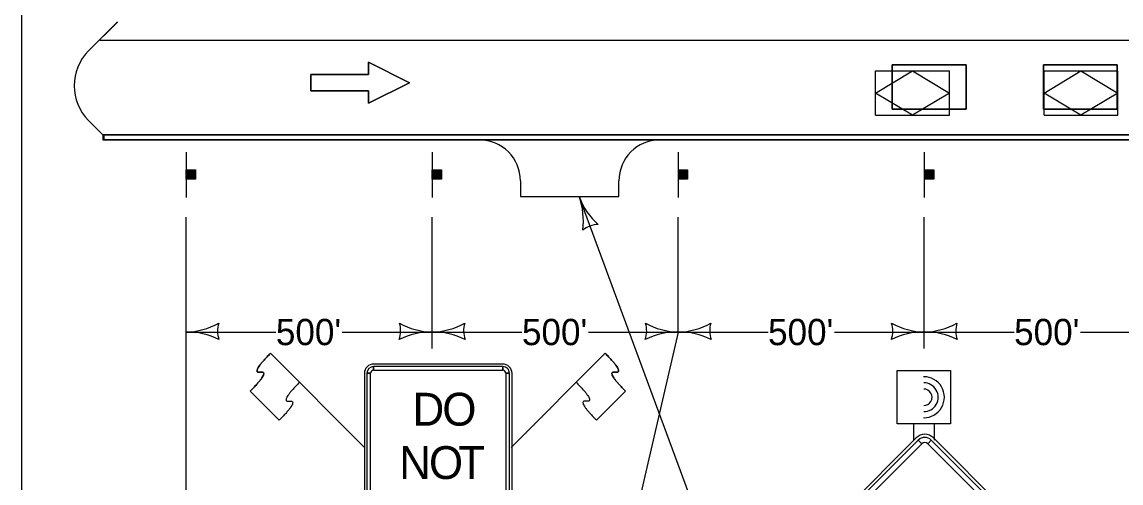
# Model space of a CAD drawing. Extents: x -2134934 to -2119606, y -2139046 to -2137036.
# Drawn here: x -2130232 to -2129562, y -2137877 to -2137596 of the extents above; entities that cross this region are included whole.
import ezdxf

# ---------------------------------------------------------------- set-up
doc = ezdxf.new("R2010")
doc.units = 0
for name, color, linetype in [('Default', 7, 'Continuous'), ('dsnCellElements', 7, 'Continuous'), ('dsnStdLabel', 7, 'Continuous'), ('dsnStdLineWork', 7, 'Continuous'), ('Level 2', 7, 'Continuous'), ('Level 4', 7, 'Continuous'), ('Level 5', 7, 'Continuous')]:
    doc.layers.add(name, color=color, linetype=linetype)

msp = doc.modelspace()

# ---------------------------------------------------------------- linework, layer by layer
at = {"layer": 'Default'}
msp.add_lwpolyline([(-2130231.95, -2137035.95), (-2127096.96, -2137035.95), (-2127096.96, -2139045.94), (-2130231.95, -2139045.94)], close=True, dxfattribs=at)
at = {"layer": 'dsnCellElements'}
for centre, radius, start, end in [((-2129932.23, -2137717.4), 42.5, 352.23545, 20.30794), ((-2129852.52, -2137687.9), 42.5, 200.30794, 228.38043), ((-2129880.01, -2137736.07), 16.42, 92.57459, 128.04129)]:
    msp.add_arc(centre, radius, start, end, dxfattribs=at)
at = {"layer": 'dsnStdLabel'}
for p, q in [((-2130023.11, -2137855.42), (-2130080.45, -2137798.12)), ((-2130080.45, -2137798.12), (-2130062.76, -2137815.8)), ((-2129933.82, -2137855.42), (-2129876.5, -2137798.11)), ((-2129876.5, -2137798.11), (-2129894.18, -2137815.79)), ((-2130023.24, -2137810.29), (-2130023.24, -2137919.04)), ((-2130021.68, -2137810.29), (-2130019.49, -2137810.29)), ((-2129938.87, -2137804.67), (-2130017.62, -2137804.67)), ((-2130017.62, -2137808.42), (-2130017.62, -2137806.23)), ((-2129938.87, -2137806.23), (-2129938.87, -2137808.42)), ((-2129936.99, -2137810.29), (-2129934.81, -2137810.29)), ((-2129933.24, -2137919.04), (-2129933.24, -2137810.29)), ((-2130075.13, -2137838.79), (-2130092.81, -2137821.12)), ((-2129881.8, -2137838.78), (-2129864.12, -2137821.1)), ((-2129686.95, -2137849.65), (-2129761.19, -2137923.9)), ((-2129685.62, -2137850.98), (-2129683.41, -2137853.19)), ((-2129679.88, -2137853.19), (-2129677.67, -2137850.98)), ((-2129602.1, -2137923.9), (-2129676.34, -2137849.65))]:
    msp.add_line(p, q, dxfattribs=at)
for points in [[(-2130021.68, -2137810.29), (-2130021.68, -2137919.04), (-2130019.49, -2137919.04), (-2130019.49, -2137810.29), (-2130021.68, -2137810.29)], [(-2129938.87, -2137806.23), (-2130017.62, -2137806.23), (-2130017.62, -2137808.42), (-2129938.87, -2137808.42), (-2129938.87, -2137806.23)], [(-2129934.81, -2137919.04), (-2129934.81, -2137810.29), (-2129936.99, -2137810.29), (-2129936.99, -2137919.04), (-2129934.81, -2137919.04)], [(-2129685.62, -2137850.98), (-2129759.87, -2137925.22), (-2129757.66, -2137927.43), (-2129683.41, -2137853.19), (-2129685.62, -2137850.98)], [(-2129603.42, -2137925.22), (-2129677.67, -2137850.98), (-2129679.88, -2137853.19), (-2129605.63, -2137927.43), (-2129603.42, -2137925.22)]]:
    msp.add_lwpolyline(points, close=True, dxfattribs=at)
for centre, radius, start, end in [((-2130017.62, -2137810.29), 5.62, 90.00021, 179.99985), ((-2130017.62, -2137810.29), 4.06, 90.00021, 179.99985), ((-2130017.62, -2137810.29), 1.87, 90.00021, 179.99985), ((-2129938.87, -2137810.29), 5.62, 0, 90.00021), ((-2129938.87, -2137810.29), 4.06, 0, 90.00021), ((-2129938.87, -2137810.29), 1.87, 0, 90.00021), ((-2129681.64, -2137854.96), 7.5, 44.99999, 134.99974), ((-2129681.64, -2137854.96), 5.62, 44.99999, 134.99974), ((-2129681.64, -2137854.96), 2.5, 44.99999, 134.99974)]:
    msp.add_arc(centre, radius, start, end, dxfattribs=at)
for points in [[(-2130092.81, -2137821.12), (-2130080.44, -2137808.74), (-2130092.82, -2137810.51), (-2130080.45, -2137798.12)], [(-2129864.12, -2137821.1), (-2129876.5, -2137808.72), (-2129864.12, -2137810.49), (-2129876.5, -2137798.11)], [(-2130062.76, -2137815.8), (-2130075.13, -2137828.19), (-2130062.76, -2137826.41), (-2130075.13, -2137838.79)], [(-2129894.18, -2137815.79), (-2129881.8, -2137828.17), (-2129894.17, -2137826.4), (-2129881.8, -2137838.78)]]:
    msp.add_open_spline(points, degree=2, dxfattribs=at)
at = {"layer": 'dsnStdLineWork'}
for p, q in [((-2129531.95, -2137607.66), (-2130184.45, -2137607.66)), ((-2129535.12, -2137665.16), (-2130182.57, -2137665.16)), ((-2130182.57, -2137665.16), (-2130182.57, -2137668.16)), ((-2130182.57, -2137668.16), (-2129497.55, -2137668.16)), ((-2130181.95, -2137665.16), (-2128681.95, -2137665.16)), ((-2130181.95, -2137668.16), (-2130181.95, -2137665.16))]:
    msp.add_line(p, q, dxfattribs=at)
for points in [[(-2128870.12, -2137665.16), (-2130182.57, -2137665.16)], [(-2128870.12, -2137668.16), (-2130182.57, -2137668.16)]]:
    msp.add_lwpolyline(points, dxfattribs=at)
at = {"layer": 'Level 2'}
for p, q in [((-2130173.78, -2137596.37), (-2130191.36, -2137613.95)), ((-2130173.79, -2137596.38), (-2130191.36, -2137613.95)), ((-2129701.47, -2137622.46), (-2129656.47, -2137622.46)), ((-2129701.47, -2137649.46), (-2129701.47, -2137622.46)), ((-2129656.47, -2137622.46), (-2129701.47, -2137622.46)), ((-2129701.47, -2137622.46), (-2129701.47, -2137649.46)), ((-2129656.47, -2137622.46), (-2129656.47, -2137649.46)), ((-2129656.47, -2137649.46), (-2129656.47, -2137622.46)), ((-2129609.28, -2137622.54), (-2129564.28, -2137622.54)), ((-2129609.28, -2137649.54), (-2129609.28, -2137622.54)), ((-2129564.28, -2137622.54), (-2129609.28, -2137622.54)), ((-2129609.28, -2137622.54), (-2129609.28, -2137649.54)), ((-2129564.28, -2137622.54), (-2129564.28, -2137649.54)), ((-2129564.28, -2137649.54), (-2129564.28, -2137622.54)), ((-2129711.63, -2137653.13), (-2129711.63, -2137626.13)), ((-2129711.63, -2137626.13), (-2129666.63, -2137626.13)), ((-2129666.63, -2137653.13), (-2129666.63, -2137626.13)), ((-2129608.95, -2137653.13), (-2129608.95, -2137626.13)), ((-2129608.95, -2137626.13), (-2129563.95, -2137626.13)), ((-2129563.95, -2137653.13), (-2129563.95, -2137626.13)), ((-2129656.47, -2137649.46), (-2129701.47, -2137649.46)), ((-2129701.47, -2137649.46), (-2129656.47, -2137649.46)), ((-2129564.28, -2137649.54), (-2129609.28, -2137649.54)), ((-2129609.28, -2137649.54), (-2129564.28, -2137649.54)), ((-2130191.36, -2137656.37), (-2130182.57, -2137665.16)), ((-2130191.36, -2137656.38), (-2130182.57, -2137665.16)), ((-2129711.63, -2137653.13), (-2129666.63, -2137653.13)), ((-2129608.95, -2137653.13), (-2129563.95, -2137653.13)), ((-2130182.57, -2137665.16), (-2128870.12, -2137665.16)), ((-2129843.13, -2137668.16), (-2129953.13, -2137668.16)), ((-2129639.46, -2137668.16), (-2129614.46, -2137668.16)), ((-2130131.95, -2137675.66), (-2130131.95, -2137703.16)), ((-2129981.95, -2137675.66), (-2129981.95, -2137703.16)), ((-2129831.95, -2137675.66), (-2129831.95, -2137703.16)), ((-2129681.95, -2137675.66), (-2129681.95, -2137703.16)), ((-2130131.54, -2137692.11), (-2130131.54, -2137686.52)), ((-2130131.26, -2137686.52), (-2130131.26, -2137692.11)), ((-2130130.99, -2137692.11), (-2130130.99, -2137686.52)), ((-2130130.73, -2137686.52), (-2130130.73, -2137692.11)), ((-2130130.51, -2137692.11), (-2130130.51, -2137686.52)), ((-2130130.3, -2137686.52), (-2130130.3, -2137692.11)), ((-2130129.96, -2137692.11), (-2130129.96, -2137686.52)), ((-2130129.7, -2137686.52), (-2130129.7, -2137692.11)), ((-2130129.47, -2137692.11), (-2130129.49, -2137686.52)), ((-2130129.16, -2137686.52), (-2130129.16, -2137692.11)), ((-2130128.78, -2137692.11), (-2130128.78, -2137686.52)), ((-2130128.35, -2137686.52), (-2130128.35, -2137692.11)), ((-2130128.12, -2137692.11), (-2130128.14, -2137686.52)), ((-2130127.71, -2137686.52), (-2130127.69, -2137692.11)), ((-2130127.49, -2137692.11), (-2130127.49, -2137686.52)), ((-2130127.17, -2137686.52), (-2130127.17, -2137692.11)), ((-2130126.94, -2137692.11), (-2130126.94, -2137686.52)), ((-2130126.62, -2137686.52), (-2130126.62, -2137692.11)), ((-2129981.54, -2137692.11), (-2129981.54, -2137686.52)), ((-2129981.26, -2137686.52), (-2129981.26, -2137692.11)), ((-2129980.99, -2137692.11), (-2129980.99, -2137686.52)), ((-2129980.73, -2137686.52), (-2129980.73, -2137692.11)), ((-2129980.51, -2137692.11), (-2129980.51, -2137686.52)), ((-2129980.3, -2137686.52), (-2129980.3, -2137692.11)), ((-2129979.96, -2137692.11), (-2129979.96, -2137686.52)), ((-2129979.7, -2137686.52), (-2129979.7, -2137692.11)), ((-2129979.47, -2137692.11), (-2129979.49, -2137686.52)), ((-2129979.16, -2137686.52), (-2129979.16, -2137692.11)), ((-2129978.78, -2137692.11), (-2129978.78, -2137686.52)), ((-2129978.35, -2137686.52), (-2129978.35, -2137692.11)), ((-2129978.12, -2137692.11), (-2129978.14, -2137686.52)), ((-2129977.71, -2137686.52), (-2129977.69, -2137692.11)), ((-2129977.49, -2137692.11), (-2129977.49, -2137686.52)), ((-2129977.17, -2137686.52), (-2129977.17, -2137692.11)), ((-2129976.94, -2137692.11), (-2129976.94, -2137686.52)), ((-2129976.62, -2137686.52), (-2129976.62, -2137692.11)), ((-2129831.54, -2137692.11), (-2129831.54, -2137686.52)), ((-2129831.26, -2137686.52), (-2129831.26, -2137692.11)), ((-2129830.99, -2137692.11), (-2129830.99, -2137686.52)), ((-2129830.73, -2137686.52), (-2129830.73, -2137692.11)), ((-2129830.51, -2137692.11), (-2129830.51, -2137686.52)), ((-2129830.3, -2137686.52), (-2129830.3, -2137692.11)), ((-2129829.96, -2137692.11), (-2129829.96, -2137686.52)), ((-2129829.7, -2137686.52), (-2129829.7, -2137692.11)), ((-2129829.47, -2137692.11), (-2129829.49, -2137686.52)), ((-2129829.16, -2137686.52), (-2129829.16, -2137692.11)), ((-2129828.78, -2137692.11), (-2129828.78, -2137686.52)), ((-2129828.35, -2137686.52), (-2129828.35, -2137692.11)), ((-2129828.12, -2137692.11), (-2129828.14, -2137686.52)), ((-2129827.71, -2137686.52), (-2129827.69, -2137692.11)), ((-2129827.49, -2137692.11), (-2129827.49, -2137686.52)), ((-2129827.17, -2137686.52), (-2129827.17, -2137692.11)), ((-2129826.94, -2137692.11), (-2129826.94, -2137686.52)), ((-2129826.62, -2137686.52), (-2129826.62, -2137692.11)), ((-2129681.54, -2137692.11), (-2129681.54, -2137686.52)), ((-2129681.26, -2137686.52), (-2129681.26, -2137692.11)), ((-2129680.99, -2137692.11), (-2129680.99, -2137686.52)), ((-2129680.73, -2137686.52), (-2129680.73, -2137692.11)), ((-2129680.51, -2137692.11), (-2129680.51, -2137686.52)), ((-2129680.3, -2137686.52), (-2129680.3, -2137692.11)), ((-2129679.96, -2137692.11), (-2129679.96, -2137686.52)), ((-2129679.7, -2137686.52), (-2129679.7, -2137692.11)), ((-2129679.48, -2137692.11), (-2129679.49, -2137686.52)), ((-2129679.16, -2137686.52), (-2129679.16, -2137692.11)), ((-2129678.78, -2137692.11), (-2129678.78, -2137686.52)), ((-2129678.35, -2137686.52), (-2129678.35, -2137692.11)), ((-2129678.13, -2137692.11), (-2129678.14, -2137686.52)), ((-2129677.71, -2137686.52), (-2129677.69, -2137692.11)), ((-2129677.49, -2137692.11), (-2129677.49, -2137686.52)), ((-2129677.17, -2137686.52), (-2129677.17, -2137692.11)), ((-2129676.94, -2137692.11), (-2129676.94, -2137686.52)), ((-2129676.63, -2137686.52), (-2129676.63, -2137692.11)), ((-2129698.37, -2138226.89), (-2129892.38, -2137702.65)), ((-2130131.95, -2137893.97), (-2130131.95, -2137715.16)), ((-2129981.95, -2137795.16), (-2129981.95, -2137715.16)), ((-2129831.95, -2137785.16), (-2129831.95, -2137715.16)), ((-2129681.95, -2137795.16), (-2129681.95, -2137715.16)), ((-2130131.95, -2137785.16), (-2130077.2, -2137785.16)), ((-2130036.7, -2137785.16), (-2129981.95, -2137785.16)), ((-2129981.95, -2137785.16), (-2129927.2, -2137785.16)), ((-2129886.7, -2137785.16), (-2129831.95, -2137785.16)), ((-2129831.95, -2137785.16), (-2129873.72, -2137964.95)), ((-2129831.95, -2137785.16), (-2129777.2, -2137785.16)), ((-2129736.7, -2137785.16), (-2129681.95, -2137785.16)), ((-2129681.95, -2137785.16), (-2129627.2, -2137785.16)), ((-2129586.7, -2137785.16), (-2129531.95, -2137785.16)), ((-2129688.49, -2137841.1), (-2129688.49, -2137851.1)), ((-2129675.99, -2137841.1), (-2129675.99, -2137851.1))]:
    msp.add_line(p, q, dxfattribs=at)
for points in [[(-2130055.82, -2137628.32), (-2130055.82, -2137638.32), (-2130020.82, -2137638.32), (-2130020.82, -2137645.82), (-2129995.82, -2137633.32), (-2130020.82, -2137620.82), (-2130020.82, -2137628.32)], [(-2130131.86, -2137692.11), (-2130131.86, -2137686.48), (-2130126.23, -2137686.48), (-2130126.23, -2137692.11)], [(-2129981.86, -2137692.11), (-2129981.86, -2137686.48), (-2129976.23, -2137686.48), (-2129976.23, -2137692.11)], [(-2129831.86, -2137692.11), (-2129831.86, -2137686.48), (-2129826.23, -2137686.48), (-2129826.23, -2137692.11)], [(-2129681.86, -2137692.11), (-2129681.86, -2137686.48), (-2129676.23, -2137686.48), (-2129676.23, -2137692.11)], [(-2129698.49, -2137841.1), (-2129698.49, -2137808.6), (-2129665.99, -2137808.6), (-2129665.99, -2137841.1)]]:
    msp.add_lwpolyline(points, close=True, dxfattribs=at)
for points in [[(-2130020.82, -2137628.32), (-2130020.82, -2137620.82), (-2129995.82, -2137633.32), (-2130020.82, -2137645.82), (-2130020.82, -2137638.32), (-2130055.82, -2137638.32), (-2130055.82, -2137628.32), (-2130020.82, -2137628.32)], [(-2129928.13, -2137693.16), (-2129928.13, -2137702.65), (-2129868.13, -2137702.65), (-2129868.13, -2137693.16)]]:
    msp.add_lwpolyline(points, dxfattribs=at)
for centre, radius, start, end in [((-2130170.14, -2137635.16), 30, 135, 225), ((-2130170.14, -2137635.16), 30, 135, 225), ((-2129953.13, -2137693.16), 25, 0, 90), ((-2129843.13, -2137693.16), 25, 90, 180), ((-2130132.71, -2137742.67), 42.5, 271.0176, 299.07249), ((-2130096.33, -2137784.54), 16.42, 163.26665, 198.73335), ((-2130017.57, -2137784.54), 16.42, 341.26665, 16.73335), ((-2129981.2, -2137742.67), 42.5, 240.92751, 268.9824), ((-2129982.71, -2137742.67), 42.5, 271.0176, 299.07249), ((-2129946.33, -2137784.54), 16.42, 163.26665, 198.73335), ((-2129867.57, -2137784.54), 16.42, 341.26665, 16.73335), ((-2129831.2, -2137742.67), 42.5, 240.92751, 268.9824), ((-2129832.71, -2137742.67), 42.5, 271.0176, 299.07249), ((-2129796.33, -2137784.54), 16.42, 163.26665, 198.73335), ((-2129717.57, -2137784.54), 16.42, 341.26665, 16.73335), ((-2129681.2, -2137742.67), 42.5, 240.92751, 268.9824), ((-2129682.71, -2137742.67), 42.5, 271.0176, 299.07249), ((-2129646.33, -2137784.54), 16.42, 163.26665, 198.73335), ((-2130131.22, -2137827.65), 42.5, 62.92751, 90.9824), ((-2129982.68, -2137827.65), 42.5, 89.0176, 117.07249), ((-2129981.22, -2137827.65), 42.5, 62.92751, 90.9824), ((-2129832.68, -2137827.65), 42.5, 89.0176, 117.07249), ((-2129831.22, -2137827.65), 42.5, 62.92751, 90.9824), ((-2129682.68, -2137827.65), 42.5, 89.0176, 117.07249), ((-2129681.22, -2137827.65), 42.5, 62.92751, 90.9824), ((-2129682.23, -2137824.87), 12.5, 269.40414, 90.54446), ((-2129682.23, -2137824.87), 12.5, 269.40414, 90.54446), ((-2129682.23, -2137824.87), 8.75, 269.40414, 90.54446), ((-2129682.23, -2137824.87), 5, 269.40414, 90.54446)]:
    msp.add_arc(centre, radius, start, end, dxfattribs=at)
at = {"layer": 'Level 4'}
for points in [[(-2129711.63, -2137639.63), (-2129689.13, -2137626.13), (-2129666.63, -2137639.63), (-2129689.13, -2137653.13)], [(-2129608.95, -2137639.63), (-2129586.45, -2137626.13), (-2129563.95, -2137639.63), (-2129586.45, -2137653.13)]]:
    msp.add_lwpolyline(points, close=True, dxfattribs=at)
at = {"layer": 'Level 5'}
for p, q in [((-2130092.81, -2137821.12), (-2130075.13, -2137838.79)), ((-2129864.12, -2137821.1), (-2129881.8, -2137838.78))]:
    msp.add_line(p, q, dxfattribs=at)
for points in [[(-2130080.45, -2137798.12), (-2130092.82, -2137810.51), (-2130080.44, -2137808.74), (-2130092.81, -2137821.12)], [(-2129876.5, -2137798.11), (-2129864.12, -2137810.49), (-2129876.5, -2137808.72), (-2129864.12, -2137821.1)], [(-2130062.76, -2137815.8), (-2130075.13, -2137828.19), (-2130062.76, -2137826.41), (-2130075.13, -2137838.79)], [(-2129894.18, -2137815.79), (-2129881.8, -2137828.17), (-2129894.17, -2137826.4), (-2129881.8, -2137838.78)]]:
    msp.add_open_spline(points, degree=2, dxfattribs=at)

# ---------------------------------------------------------------- texts
at = {"layer": 'dsnStdLabel'}
for s, p in [('D', (-2129993.87, -2137842.17)), ('O', (-2129975.74, -2137842.17)), ('N', (-2130001.99, -2137874.67)), ('O', (-2129983.87, -2137874.67)), ('T', (-2129966.06, -2137874.67))]:
    msp.add_text(s, height=20, dxfattribs=at).set_placement(p)
at = {"layer": 'Level 2'}
for p in [(-2130077.2, -2137793.16), (-2129927.2, -2137793.16), (-2129777.2, -2137793.16), (-2129627.2, -2137793.16)]:
    msp.add_text("500'", height=16, dxfattribs=at).set_placement(p)

doc.saveas('drawing.dxf')
